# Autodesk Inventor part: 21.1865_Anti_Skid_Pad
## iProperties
Created: 2010-01
Part Number: 21.1865_Anti_Skid_Pad
Material: Rubber
Document SubType Name: Modeling
Designer: Administrator
Mass: 5.71967 g
Surface Area: 29.0675 cm^2
Volume: 6.15019 cm^3
Density: 0.93 g/cm^3
Author: Administrator
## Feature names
1. Extrusion1
2. Extrusion2
3. Fillet1
